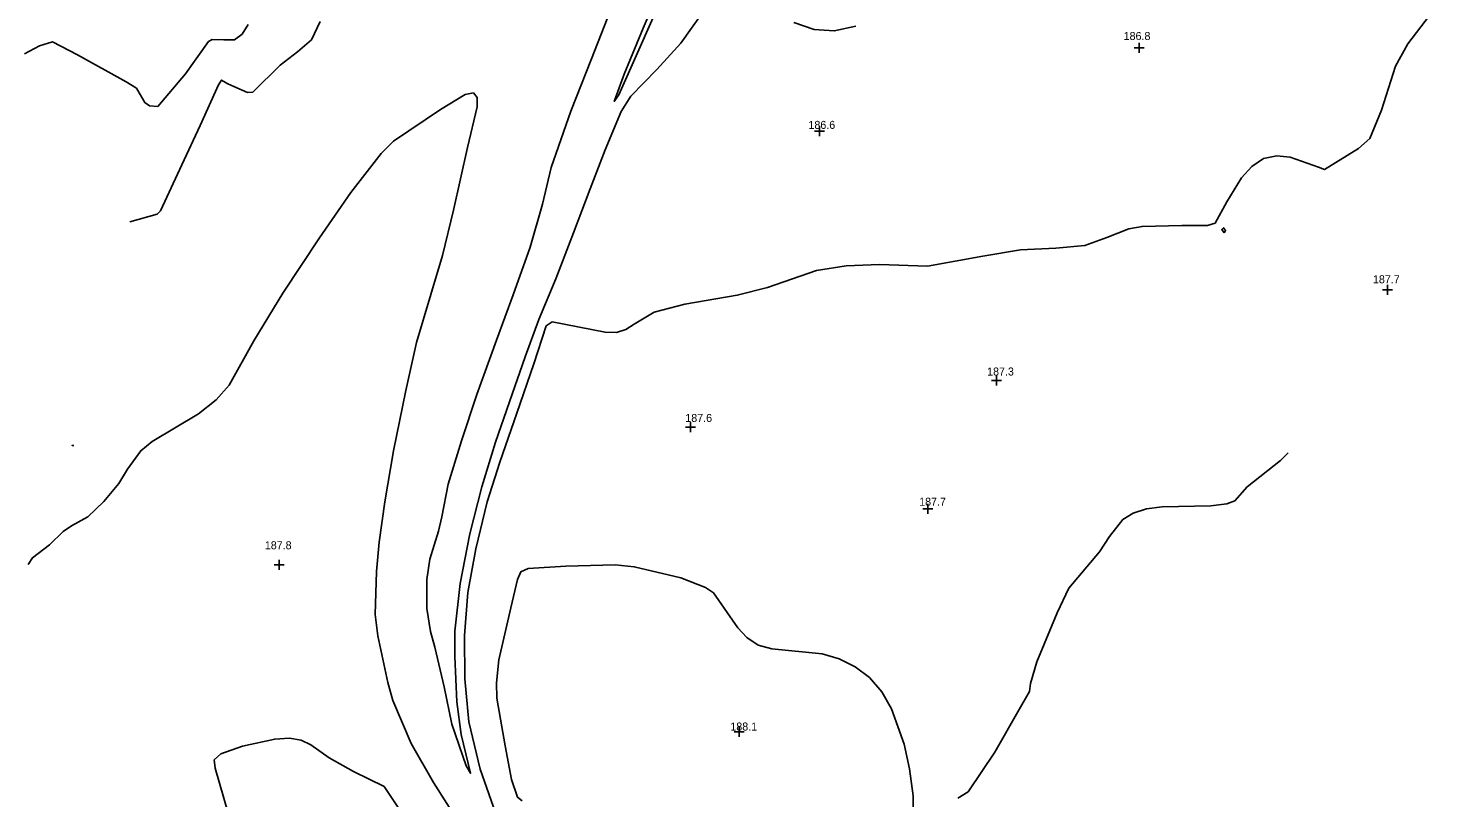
# Model space of a CAD drawing. Extents: x 1475150 to 2003689, y 770235 to 1112803.
# Drawn here: x 1992351.2 to 1992702.7, y 779596.3 to 779788.9 of the extents above; entities that cross this region are included whole.
import ezdxf

# ---------------------------------------------------------------- set-up
doc = ezdxf.new("R2010")
doc.units = 0
for name, color, linetype in [('RD_DTM_Major1', 7, 'Continuous'), ('RD_DTM_Minor1', 7, 'Continuous'), ('RD_DTM_Spot_Elev', 7, 'Continuous'), ('RD_TX_Misc1', 7, 'Continuous')]:
    doc.layers.add(name, color=color, linetype=linetype)

msp = doc.modelspace()

# ---------------------------------------------------------------- linework, layer by layer
at = {"layer": 'RD_DTM_Major1'}
for points in [[(1992509.06, 779795.13), (1992504.28, 779784.18), (1992498.93, 779772.17), (1992497.77, 779770.56), (1992500.24, 779777.38), (1992505.03, 779788.89), (1992510.21, 779801.09)], [(1992406.24, 779789.81), (1992404.72, 779787.35), (1992402.84, 779785.93), (1992400.21, 779785.98), (1992397.22, 779786.08), (1992396.37, 779785.57), (1992390.56, 779777.43), (1992383.67, 779769.28), (1992381.6, 779769.49), (1992380.45, 779770.28), (1992378.7, 779773.28), (1992378.3, 779773.84), (1992375.78, 779775.44), (1992363.55, 779782.18), (1992357.37, 779785.48), (1992354.13, 779784.49), (1992350.33, 779782.44)]]:
    msp.add_lwpolyline(points, dxfattribs=at)
at = {"layer": 'RD_DTM_Minor1'}
for points in [[(1992520.2, 779793.21), (1992514.44, 779785.09), (1992508.42, 779778.52), (1992501.93, 779771.84), (1992499.53, 779768.02), (1992495.53, 779758.44), (1992491.78, 779748.67), (1992487.6, 779737.67), (1992483.21, 779726.14), (1992478.94, 779716.05), (1992475.47, 779706.69), (1992471.55, 779695.38), (1992468.12, 779685.3), (1992464.64, 779674.12), (1992461.67, 779662.41), (1992459.25, 779649.97), (1992457.96, 779638.07), (1992457.9, 779631.69), (1992458.45, 779620.41), (1992459.54, 779612.19), (1992461.84, 779602.53), (1992460.77, 779604.34), (1992457.16, 779614.8), (1992455.22, 779624.13), (1992452.88, 779634.06), (1992451.85, 779638), (1992450.95, 779643.7), (1992450.91, 779651.01), (1992451.7, 779656.09), (1992453.86, 779663.04), (1992454.7, 779666.62), (1992456.27, 779674.8), (1992459.61, 779685.68), (1992463.43, 779697.24), (1992468.3, 779710.87), (1992472.5, 779722.2), (1992476.73, 779734.14), (1992479.81, 779744.84), (1992481.98, 779754.04), (1992486.89, 779768.09), (1992492.08, 779781.22), (1992497.63, 779795.47)], [(1992702.68, 779793.5), (1992696.14, 779784.97), (1992693.09, 779779.37), (1992689.55, 779768.33), (1992686.69, 779761.26), (1992683.83, 779758.8), (1992675.34, 779753.5), (1992673.83, 779754.13), (1992666.75, 779756.61), (1992663.41, 779756.93), (1992660.12, 779756.25), (1992657.16, 779754.27), (1992654.62, 779751.41), (1992650.95, 779745.42), (1992647.97, 779740.13), (1992646.1, 779739.48), (1992639.67, 779739.51), (1992629.72, 779739.3), (1992626.41, 779738.71), (1992620.94, 779736.54), (1992615.42, 779734.48), (1992608.18, 779733.83), (1992599.37, 779733.4), (1992589.92, 779731.88), (1992576.09, 779729.38), (1992564.06, 779729.78), (1992555.74, 779729.47), (1992548.32, 779728.26), (1992536.12, 779724.03), (1992528.53, 779722.09), (1992515.38, 779719.85), (1992507.72, 779717.86), (1992502.75, 779714.81), (1992500.65, 779713.49), (1992498.32, 779712.75), (1992495.49, 779712.82), (1992482.23, 779715.41), (1992480.75, 779714.41), (1992477.63, 779704.89), (1992473.44, 779692.61), (1992469.13, 779680.35), (1992465.98, 779670.38), (1992463.16, 779658.65), (1992461.13, 779647.74), (1992460.31, 779636.99), (1992460.39, 779626.14), (1992461.46, 779615.38), (1992464.22, 779603.56), (1992468.11, 779592.6)], [(1992424.25, 779790.51), (1992422.05, 779785.97), (1992418.55, 779783), (1992414.22, 779779.59), (1992407.43, 779772.9), (1992406.11, 779772.76), (1992402.67, 779774.29), (1992401.14, 779774.93), (1992399.61, 779775.88), (1992398.87, 779774.73), (1992394.28, 779764.56), (1992389.65, 779754.72), (1992384.37, 779743.22), (1992383.49, 779742.32), (1992376.66, 779740.43)], [(1992558.16, 779789.42), (1992552.78, 779788.21), (1992547.76, 779788.55), (1992542.7, 779790.28)], [(1992458.65, 779590.6), (1992452.61, 779600.22), (1992447.02, 779609.98), (1992442.4, 779620.69), (1992441.18, 779625.22), (1992438.66, 779636.85), (1992437.98, 779642.18), (1992438.36, 779652.96), (1992438.99, 779660.31), (1992440.46, 779670.37), (1992442.57, 779683.15), (1992445.63, 779698.25), (1992448.33, 779710.27), (1992451.94, 779722.23), (1992454.85, 779732.03), (1992457.62, 779743.39), (1992461.08, 779759), (1992463.49, 779769.18), (1992463.49, 779771.52), (1992462.57, 779772.7), (1992460.51, 779772.3), (1992454.31, 779768.52), (1992442.6, 779760.6), (1992439.5, 779757.49), (1992431.96, 779747.79), (1992424.1, 779736.4), (1992414.93, 779722.6), (1992407.69, 779710.67), (1992401.52, 779699.55), (1992398.27, 779695.94), (1992393.8, 779692.39), (1992382.27, 779685.52), (1992379.39, 779683.18), (1992376.09, 779678.58), (1992373.89, 779674.98), (1992370.17, 779670.47), (1992366.21, 779666.68), (1992362.09, 779664.43), (1992360.01, 779662.99), (1992356.55, 779659.66), (1992352.3, 779656.41), (1992351.23, 779654.73)], [(1992650.21, 779737.69), (1992649.65, 779738.51), (1992650.06, 779738.95), (1992650.6, 779738.28), (1992650.21, 779737.69)], [(1992362.67, 779684.52), (1992362.23, 779684.51), (1992362.67, 779684.52)], [(1992666.27, 779682.63), (1992664.35, 779680.74), (1992655.99, 779674.17), (1992652.95, 779670.65), (1992650.94, 779669.86), (1992646.88, 779669.43), (1992634.72, 779669.17), (1992630.86, 779668.64), (1992627.48, 779667.6), (1992624.91, 779665.97), (1992621.57, 779661.73), (1992619.07, 779657.87), (1992611.45, 779648.8), (1992608.52, 779642.63), (1992603.45, 779630.37), (1992601.86, 779625), (1992601.55, 779622.98), (1992599.03, 779618.44), (1992592.92, 779607.8), (1992586.26, 779597.87), (1992583.64, 779596.24)], [(1992572.53, 779586.12), (1992572.51, 779596.86), (1992571.62, 779603.58), (1992570.21, 779609.8), (1992567.07, 779618.66), (1992564.65, 779622.89), (1992561.58, 779626.42), (1992557.97, 779629.17), (1992553.97, 779631.15), (1992549.72, 779632.38), (1992537.18, 779633.6), (1992533.73, 779634.57), (1992530.94, 779636.43), (1992528.71, 779638.9), (1992522.55, 779647.65), (1992520.62, 779648.95), (1992514.41, 779651.35), (1992502.79, 779654.18), (1992498.02, 779654.62), (1992485.7, 779654.29), (1992476.28, 779653.69), (1992474.38, 779652.86), (1992473.59, 779651), (1992471.88, 779643.88), (1992468.96, 779630.89), (1992468.33, 779625.11), (1992468.41, 779621.27), (1992470.52, 779609.37), (1992472.07, 779600.94), (1992473.56, 779596.5), (1992474.72, 779595.64)], [(1992447.06, 779588.96), (1992440.24, 779599.19), (1992432.56, 779602.95), (1992426.53, 779606.37), (1992421.91, 779609.63), (1992419.54, 779610.76), (1992416.62, 779611.27), (1992412.9, 779611.05), (1992404.83, 779609.26), (1992399.41, 779607.37), (1992397.77, 779605.88), (1992397.98, 779603.75), (1992401.25, 779592.5)]]:
    msp.add_lwpolyline(points, dxfattribs=at)
at = {"layer": 'RD_DTM_Spot_Elev'}
for p, q in [((1992628.98, 779782.69), (1992628.98, 779785.19)), ((1992627.73, 779783.94), (1992630.23, 779783.94)), ((1992547.8, 779763.12), (1992550.3, 779763.12)), ((1992549.05, 779761.87), (1992549.05, 779764.37)), ((1992691.07, 779722.18), (1992691.07, 779724.68)), ((1992689.82, 779723.43), (1992692.32, 779723.43)), ((1992592.11, 779700.71), (1992594.61, 779700.71)), ((1992593.36, 779699.46), (1992593.36, 779701.96)), ((1992516.8, 779687.82), (1992516.8, 779690.32)), ((1992515.55, 779689.07), (1992518.05, 779689.07)), ((1992574.9, 779668.66), (1992577.4, 779668.66)), ((1992576.15, 779667.41), (1992576.15, 779669.91)), ((1992412.75, 779654.64), (1992415.25, 779654.64)), ((1992414, 779653.39), (1992414, 779655.89)), ((1992527.77, 779612.86), (1992530.27, 779612.86)), ((1992529.02, 779611.61), (1992529.02, 779614.11))]:
    msp.add_line(p, q, dxfattribs=at)

# ---------------------------------------------------------------- texts
at = {"layer": 'RD_TX_Misc1'}
for s, p in [('186.8', (1992625.12, 779785.92)), ('186.6', (1992546.32, 779763.69)), ('187.7', (1992687.44, 779725.07)), ('187.3', (1992590.99, 779702)), ('187.6', (1992515.54, 779690.38)), ('187.7', (1992574, 779669.43)), ('187.8', (1992410.42, 779658.54)), ('188.1', (1992526.8, 779613.2))]:
    msp.add_text(s, height=2, dxfattribs=at).set_placement(p)

doc.saveas('drawing.dxf')
